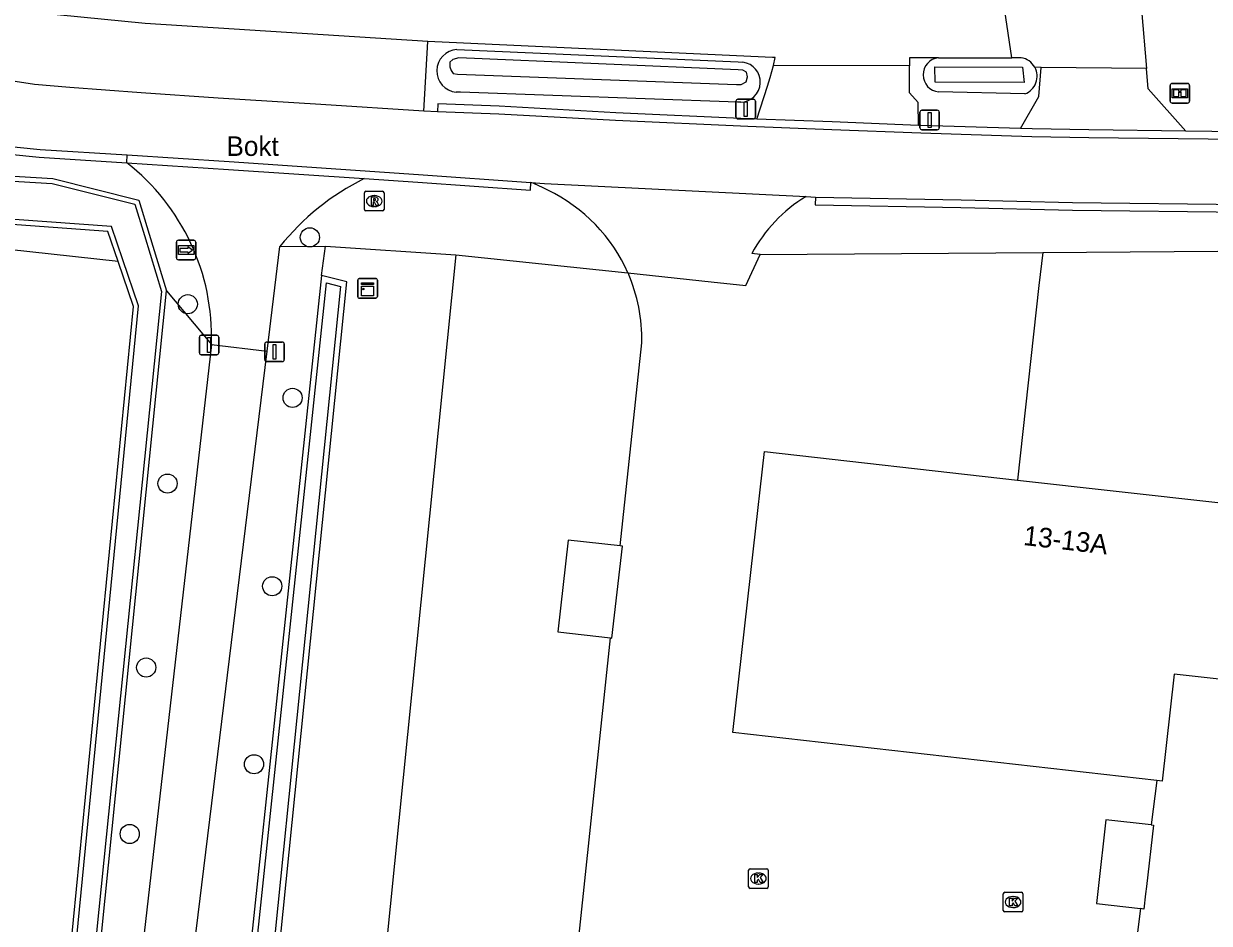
# Model space of a CAD drawing. Extents: x 162515 to 163909, y 388494 to 389773.
# Drawn here: x 162964.9 to 163025.4, y 388929.3 to 388975.3 of the extents above; entities that cross this region are included whole.
import ezdxf

# ---------------------------------------------------------------- set-up
doc = ezdxf.new("R2010")
doc.units = 0
for name, color, linetype in [('IMGEO_Afsluitpaal', 7, 'Continuous'), ('IMGEO_Boom', 7, 'Continuous'), ('IMGEO_Erf', 7, 'Continuous'), ('IMGEO_Grasland_agrarisch', 7, 'Continuous'), ('IMGEO_Grasland_overig', 7, 'Continuous'), ('IMGEO_Groenvoorziening', 7, 'Continuous'), ('IMGEO_Informatiebord', 7, 'Continuous'), ('IMGEO_Kast', 7, 'Continuous'), ('IMGEO_Kolk', 7, 'Continuous'), ('IMGEO_Loofbos', 7, 'Continuous'), ('IMGEO_Openbare_ruimte_label', 7, 'Continuous'), ('IMGEO_Pand', 7, 'Continuous'), ('IMGEO_Pand_nummerreeks', 7, 'Continuous'), ('IMGEO_Rijbaan_lokaal_gesloten', 7, 'Continuous'), ('IMGEO_Rijbaan_lokaal_halfverhard', 7, 'Continuous'), ('IMGEO_Rijbaan_lokaal_onverhard', 7, 'Continuous'), ('IMGEO_Rijbaan_lokaal_open', 7, 'Continuous'), ('IMGEO_Rioolput', 7, 'Continuous'), ('IMGEO_Waterloop', 7, 'Continuous'), ('IMGEO_Wegwijzer', 7, 'Continuous')]:
    doc.layers.add(name, color=color, linetype=linetype)

msp = doc.modelspace()

# ---------------------------------------------------------------- linework, layer by layer
at = {"layer": 'IMGEO_Afsluitpaal'}
for p, q in [((163001.263, 388970.503), (163001.263, 388971.303)), ((163001.263, 388971.303), (163001.263, 388970.503)), ((163001.363, 388971.403), (163002.153, 388971.403)), ((163002.153, 388971.403), (163001.363, 388971.403)), ((163002.253, 388971.303), (163002.253, 388970.503)), ((163002.253, 388970.503), (163002.253, 388971.303)), ((163010.652, 388969.946), (163010.652, 388970.746)), ((163010.652, 388970.746), (163010.652, 388969.946)), ((163010.752, 388970.846), (163011.542, 388970.846)), ((163011.542, 388970.846), (163010.752, 388970.846)), ((163011.642, 388970.746), (163011.642, 388969.946)), ((163011.642, 388969.946), (163011.642, 388970.746)), ((163002.153, 388970.403), (163001.363, 388970.403)), ((163001.363, 388970.403), (163002.153, 388970.403)), ((163011.542, 388969.846), (163010.752, 388969.846)), ((163010.752, 388969.846), (163011.542, 388969.846)), ((162973.867, 388958.456), (162973.867, 388959.256)), ((162973.867, 388959.256), (162973.867, 388958.456)), ((162973.967, 388959.356), (162974.757, 388959.356)), ((162974.757, 388959.356), (162973.967, 388959.356)), ((162974.857, 388959.256), (162974.857, 388958.456)), ((162974.857, 388958.456), (162974.857, 388959.256)), ((162977.21, 388958.108), (162977.21, 388958.908)), ((162977.21, 388958.908), (162977.21, 388958.108)), ((162977.31, 388959.008), (162978.1, 388959.008)), ((162978.1, 388959.008), (162977.31, 388959.008)), ((162978.2, 388958.908), (162978.2, 388958.108)), ((162978.2, 388958.108), (162978.2, 388958.908)), ((162974.757, 388958.356), (162973.967, 388958.356)), ((162973.967, 388958.356), (162974.757, 388958.356)), ((162978.1, 388958.008), (162977.31, 388958.008)), ((162977.31, 388958.008), (162978.1, 388958.008))]:
    msp.add_line(p, q, dxfattribs=at)
for points in [[(163001.683, 388971.278), (163001.833, 388971.278), (163001.833, 388970.528), (163001.683, 388970.528), (163001.683, 388971.278)], [(163011.072, 388970.721), (163011.222, 388970.721), (163011.222, 388969.971), (163011.072, 388969.971), (163011.072, 388970.721)], [(162974.287, 388959.231), (162974.437, 388959.231), (162974.437, 388958.481), (162974.287, 388958.481), (162974.287, 388959.231)], [(162977.63, 388958.883), (162977.78, 388958.883), (162977.78, 388958.133), (162977.63, 388958.133), (162977.63, 388958.883)]]:
    msp.add_lwpolyline(points, dxfattribs=at)
for centre, start, end in [((163001.363, 388971.303), 90, 180), ((163001.363, 388971.303), 90, 180), ((163002.153, 388971.303), 0, 90), ((163002.153, 388971.303), 360, 90), ((163010.752, 388970.746), 90, 180), ((163010.752, 388970.746), 90, 180), ((163011.542, 388970.746), 0, 90), ((163011.542, 388970.746), 360, 90), ((163001.363, 388970.503), 180, 270), ((163001.363, 388970.503), 180, 270), ((163002.153, 388970.503), 270, 0), ((163002.153, 388970.503), 270, 0), ((163010.752, 388969.946), 180, 270), ((163010.752, 388969.946), 180, 270), ((163011.542, 388969.946), 270, 0), ((163011.542, 388969.946), 270, 0), ((162973.967, 388959.256), 90, 180), ((162973.967, 388959.256), 90, 180), ((162974.757, 388959.256), 0, 90), ((162974.757, 388959.256), 360, 90), ((162977.31, 388958.908), 90, 180), ((162977.31, 388958.908), 90, 180), ((162978.1, 388958.908), 0, 90), ((162978.1, 388958.908), 360, 90), ((162973.967, 388958.456), 180, 270), ((162973.967, 388958.456), 180, 270), ((162974.757, 388958.456), 270, 0), ((162974.757, 388958.456), 270, 0), ((162977.31, 388958.108), 180, 270), ((162977.31, 388958.108), 180, 270), ((162978.1, 388958.108), 270, 0), ((162978.1, 388958.108), 270, 0)]:
    msp.add_arc(centre, 0.1, start, end, dxfattribs=at)
at = {"layer": 'IMGEO_Boom'}
for centre in [(162979.51, 388964.352), (162973.276, 388960.939), (162978.627, 388956.157), (162972.241, 388951.779), (162977.588, 388946.536), (162971.154, 388942.386), (162976.658, 388937.446), (162970.312, 388933.887)]:
    msp.add_circle(centre, 0.489, dxfattribs=at)
at = {"layer": 'IMGEO_Erf'}
for points in [[(163015.346, 388973.525), (163010.383, 389006.948)], [(163011.598, 388973.525), (163015.346, 388973.525)], [(163015.826, 388973.525), (163015.346, 388973.525)], [(163016.933, 388963.586), (163016.732, 388961.895), (163015.629, 388951.954)], [(162995.356, 388948.595), (162996.452, 388958.963)], [(162990.226, 388900.063), (162994.86, 388943.901)], [(163022.747, 388936.621), (163022.461, 388934.353)], [(163021.922, 388930.074), (163020.882, 388921.826), (163013.048, 388922.764)]]:
    msp.add_lwpolyline(points, dxfattribs=at)
for centre, radius, start, end in [((163015.679, 388972.578), 0.958, 28.60141, 81.17112), ((162988.096, 388959.176), 8.359, 358.54008, 23.67827)]:
    msp.add_arc(centre, radius, start, end, dxfattribs=at)
at = {"layer": 'IMGEO_Grasland_agrarisch'}
msp.add_lwpolyline([(162965.269, 388906.51), (162965.295, 388907.571), (162970.507, 388960.823), (162969.722, 388963.115)], dxfattribs=at)
at = {"layer": 'IMGEO_Grasland_overig'}
for points in [[(163021.967, 388975.964), (163022.225, 388972.97)], [(162925.982, 388975.254), (162939.232, 388969.776), (162946.964, 388968.638), (162951.321, 388968.254), (162966.391, 388967.363), (162970.783, 388966.255), (162971.31, 388964.515), (162972.188, 388961.62)], [(162969.722, 388963.115), (162969.194, 388964.658), (162943.616, 388966.516), (162926.272, 388973.119), (162925.379, 388974.383)], [(163003.178, 388973.126), (163003.268, 388973.532), (163003.132, 388973.537), (162985.891, 388974.332), (162985.529, 388974.355)], [(162987.016, 388973.945), (163001.376, 388973.31), (163001.616, 388973.299)], [(163011.598, 388973.525), (163010.129, 388973.525), (163010.129, 388973.107)], [(162969.722, 388963.115), (162943.576, 388965.984), (162934.148, 388968.56), (162924.889, 388971.244), (162921.313, 388972.477), (162913.718, 388966.327), (162905.083, 388967.364), (162899.047, 388963.626), (162890.416, 388958.224), (162881.009, 388955.532), (162875.047, 388956.022), (162874.432, 388960.337)], [(163016.852, 388973.034), (163016.52, 388973.037)], [(163001.508, 388971.256), (163001.35, 388971.262), (162987.194, 388971.761), (162986.975, 388971.769)], [(163016.018, 388971.682), (163011.61, 388971.781)], [(162977.98, 388963.885), (162980.313, 388963.907)], [(162986.956, 388963.458), (162995.751, 388962.533)], [(163002.495, 388963.475), (163016.933, 388963.586)], [(163016.933, 388963.586), (163037.03, 388963.741), (163052.129, 388961.909), (163052.955, 388961.925)], [(162972.188, 388961.62), (162974.481, 388958.888)]]:
    msp.add_lwpolyline(points, dxfattribs=at)
for centre, radius, start, end in [((162987.077, 388972.855), 1.091, 93.19275, 264.64839), ((163001.478, 388972.282), 1.026, 271.69795, 82.24998), ((163011.698, 388972.654), 0.877, 96.55393, 264.23453), ((163015.683, 388972.577), 0.956, 290.54795, 28.79476)]:
    msp.add_arc(centre, radius, start, end, dxfattribs=at)
at = {"layer": 'IMGEO_Groenvoorziening'}
for points in [[(162980.096, 388962.403), (162974.2, 388906.548)], [(162966.787, 388908.195), (162972.188, 388961.62)]]:
    msp.add_lwpolyline(points, dxfattribs=at)
at = {"layer": 'IMGEO_Informatiebord'}
for p, q in [((163023.432, 388971.313), (163023.432, 388972.113)), ((163023.432, 388972.113), (163023.432, 388971.313)), ((163023.532, 388972.213), (163024.322, 388972.213)), ((163024.322, 388972.213), (163023.532, 388972.213)), ((163024.422, 388972.113), (163024.422, 388971.313)), ((163024.422, 388971.313), (163024.422, 388972.113)), ((163024.322, 388971.213), (163023.532, 388971.213)), ((163023.532, 388971.213), (163024.322, 388971.213))]:
    msp.add_line(p, q, dxfattribs=at)
for points in [[(163023.533, 388971.945), (163024.321, 388971.945), (163024.321, 388971.481), (163023.533, 388971.481), (163023.533, 388971.945)], [(163023.598, 388971.88), (163023.598, 388971.546), (163023.873, 388971.546), (163023.874, 388971.759), (163023.978, 388971.76), (163023.979, 388971.546), (163024.256, 388971.546), (163024.256, 388971.88), (163023.98, 388971.88), (163023.98, 388971.8), (163023.874, 388971.8), (163023.874, 388971.88), (163023.598, 388971.88)]]:
    msp.add_lwpolyline(points, dxfattribs=at)
for centre, start, end in [((163023.532, 388972.113), 90, 180), ((163023.532, 388972.113), 90, 180), ((163024.322, 388972.113), 0, 90), ((163024.322, 388972.113), 360, 90), ((163023.532, 388971.313), 180, 270), ((163023.532, 388971.313), 180, 270), ((163024.322, 388971.313), 270, 0), ((163024.322, 388971.313), 270, 0)]:
    msp.add_arc(centre, 0.1, start, end, dxfattribs=at)
at = {"layer": 'IMGEO_Kast'}
for p, q in [((162982.03, 388962.249), (162982.871, 388962.249)), ((162982.871, 388962.249), (162982.03, 388962.249)), ((162981.955, 388961.324), (162981.955, 388962.165)), ((162981.955, 388962.165), (162981.955, 388961.324)), ((162982.955, 388962.174), (162982.955, 388961.333)), ((162982.955, 388961.333), (162982.955, 388962.174)), ((162982.88, 388961.249), (162982.039, 388961.249)), ((162982.039, 388961.249), (162982.88, 388961.249))]:
    msp.add_line(p, q, dxfattribs=at)
for points in [[(162982.15, 388962.039), (162982.75, 388962.039), (162982.75, 388961.954), (162982.15, 388961.954), (162982.15, 388962.039)], [(162982.15, 388961.864), (162982.75, 388961.864), (162982.75, 388961.375), (162982.15, 388961.375), (162982.15, 388961.864)]]:
    msp.add_lwpolyline(points, dxfattribs=at)
msp.add_circle((162982.234, 388961.713), 0.0377, dxfattribs=at)
for centre, start, end in [((162982.033, 388962.171), 92.4484, 184.28452), ((162982.033, 388962.171), 92.4484, 184.28452), ((162982.877, 388962.171), 2.4484, 94.28452), ((162982.877, 388962.171), 2.4484, 94.28452), ((162982.033, 388961.327), 182.4484, 274.28452), ((162982.033, 388961.327), 182.4484, 274.28452), ((162982.877, 388961.327), 272.4484, 4.28452), ((162982.877, 388961.327), 272.4484, 4.28452)]:
    msp.add_arc(centre, 0.0779, start, end, dxfattribs=at)
at = {"layer": 'IMGEO_Kolk'}
for p, q in [((163001.909, 388931.184), (163001.909, 388932.036)), ((163001.984, 388932.11), (163002.836, 388932.11)), ((163002.91, 388932.036), (163002.91, 388931.184)), ((163002.42, 388931.33), (163002.395, 388931.33)), ((163002.397, 388931.89), (163002.422, 388931.89)), ((163002.836, 388931.11), (163001.984, 388931.11)), ((163014.913, 388929.984), (163014.913, 388930.836)), ((163014.988, 388930.91), (163015.84, 388930.91)), ((163015.914, 388930.836), (163015.914, 388929.984)), ((163015.424, 388930.13), (163015.399, 388930.13)), ((163015.401, 388930.69), (163015.426, 388930.69)), ((163015.84, 388929.91), (163014.988, 388929.91))]:
    msp.add_line(p, q, dxfattribs=at)
for points in [[(163001.909, 388931.184), (163001.909, 388932.036)], [(163001.984, 388932.11), (163002.836, 388932.11)], [(163002.91, 388932.036), (163002.91, 388931.184)], [(163002.23, 388931.81), (163002.353, 388931.81), (163002.353, 388931.659), (163002.483, 388931.81), (163002.647, 388931.81), (163002.501, 388931.659), (163002.654, 388931.41), (163002.502, 388931.41), (163002.417, 388931.574), (163002.353, 388931.507), (163002.353, 388931.41), (163002.23, 388931.41), (163002.23, 388931.81)], [(163002.836, 388931.11), (163001.984, 388931.11)], [(163014.913, 388929.984), (163014.913, 388930.836)], [(163014.988, 388930.91), (163015.84, 388930.91)], [(163015.914, 388930.836), (163015.914, 388929.984)], [(163015.234, 388930.61), (163015.357, 388930.61), (163015.357, 388930.459), (163015.487, 388930.61), (163015.651, 388930.61), (163015.505, 388930.459), (163015.658, 388930.21), (163015.506, 388930.21), (163015.421, 388930.374), (163015.357, 388930.307), (163015.357, 388930.21), (163015.234, 388930.21), (163015.234, 388930.61)], [(163015.84, 388929.91), (163014.988, 388929.91)]]:
    msp.add_lwpolyline(points, dxfattribs=at)
for centre, start, end in [((163001.986, 388932.034), 91.55205, 178.44795), ((163001.986, 388932.034), 91.55205, 178.44795), ((163002.834, 388932.034), 1.55205, 88.44795), ((163002.834, 388932.034), 1.55205, 88.44795), ((163001.986, 388931.186), 181.55205, 268.44795), ((163001.986, 388931.186), 181.55205, 268.44795), ((163002.834, 388931.186), 271.55205, 358.44795), ((163002.834, 388931.186), 271.55205, 358.44795), ((163014.99, 388930.834), 91.55205, 178.44795), ((163014.99, 388930.834), 91.55205, 178.44795), ((163015.838, 388930.834), 1.55205, 88.44795), ((163015.838, 388930.834), 1.55205, 88.44795), ((163014.99, 388929.986), 181.55205, 268.44795), ((163014.99, 388929.986), 181.55205, 268.44795), ((163015.838, 388929.986), 271.55205, 358.44795), ((163015.838, 388929.986), 271.55205, 358.44795)]:
    msp.add_arc(centre, 0.0765, start, end, dxfattribs=at)
for centre, major_axis, ratio, start_param, end_param in [((163002.396, 388931.61), (-0.387, 0.002), 0.722429, 4.712389, 7.853982), ((163002.421, 388931.61), (-0.39, 0.002), 0.717154, 1.570796, 4.712389), ((163015.4, 388930.41), (-0.387, 0.002), 0.722429, 4.712389, 7.853982), ((163015.425, 388930.41), (-0.39, 0.002), 0.717154, 1.570796, 4.712389)]:
    msp.add_ellipse(centre, major_axis=major_axis, ratio=ratio, start_param=start_param, end_param=end_param, dxfattribs=at)
at = {"layer": 'IMGEO_Loofbos'}
for points in [[(162980.096, 388962.403), (162980.313, 388963.907)], [(162980.313, 388963.907), (162986.956, 388963.458)], [(162986.956, 388963.458), (162980.697, 388901.303), (162990.226, 388900.063)], [(162975.806, 388906.861), (162981.389, 388962.074), (162980.096, 388962.403)]]:
    msp.add_lwpolyline(points, dxfattribs=at)
at = {"layer": 'IMGEO_Pand'}
for points in [[(163022.747, 388936.621), (163001.105, 388939.069), (163002.165, 388948.444), (163002.726, 388953.412), (163015.629, 388951.954)], [(163015.629, 388951.954), (163036.085, 388949.677), (163035.083, 388940.766), (163023.643, 388942.053), (163023.027, 388936.591), (163022.747, 388936.621)], [(162995.356, 388948.595), (162992.701, 388948.895), (162992.171, 388944.205), (162994.86, 388943.901)], [(162994.86, 388943.901), (162994.932, 388943.893), (162995.462, 388948.583), (162995.356, 388948.595)], [(163022.461, 388934.353), (163020.152, 388934.613), (163019.756, 388931.104), (163019.669, 388930.328), (163021.922, 388930.074)], [(163022.461, 388934.353), (163022.572, 388934.34), (163022.219, 388931.205), (163022.177, 388930.832), (163022.089, 388930.055), (163021.922, 388930.074)]]:
    msp.add_lwpolyline(points, dxfattribs=at)
at = {"layer": 'IMGEO_Rijbaan_lokaal_gesloten'}
for points in [[(162985.329, 388970.797), (162980.065, 388971.129), (162974.827, 388971.464), (162970.89, 388971.741), (162967.254, 388971.997), (162965.448, 388972.167), (162962.802, 388972.559)], [(162947.161, 388970.98), (162953.292, 388970.102), (162965.732, 388968.844), (162970.174, 388968.559)], [(162986.023, 388970.77), (162985.329, 388970.797)], [(163060.658, 388969.221), (163043.395, 388969.279), (163026.878, 388969.344), (163019.275, 388969.441), (163016.375, 388969.489), (163010.694, 388969.666), (163006.164, 388969.852), (163001.869, 388970.009), (162995.115, 388970.321), (162989.16, 388970.649), (162986.023, 388970.77)], [(162970.174, 388968.559), (162975.389, 388968.225), (162985.053, 388967.564), (162990.798, 388967.159)], [(162990.798, 388967.159), (162991.481, 388967.111), (163004.846, 388966.436)], [(163004.846, 388966.436), (163005.318, 388966.412)], [(163005.318, 388966.412), (163012.759, 388966.272), (163018.447, 388966.138), (163027.251, 388966.034), (163035.819, 388965.997), (163049.064, 388965.828), (163059.249, 388965.846), (163068.574, 388965.898)]]:
    msp.add_lwpolyline(points, dxfattribs=at)
at = {"layer": 'IMGEO_Rijbaan_lokaal_halfverhard'}
for points in [[(163002.329, 388970.393), (163001.887, 388970.409), (162995.137, 388970.72), (162989.175, 388971.049), (162986.049, 388971.17), (162986.023, 388970.77)], [(162947.107, 388970.584), (162953.235, 388969.706), (162965.692, 388968.446), (162970.158, 388968.16)], [(163015.793, 388969.908), (163010.71, 388970.066), (163010.586, 388970.071)], [(163060.659, 388969.621), (163043.397, 388969.679), (163026.883, 388969.744), (163024.225, 388969.778)], [(162970.158, 388968.16), (162970.174, 388968.559)], [(162970.158, 388968.16), (162975.363, 388967.826), (162982.289, 388967.352)], [(162982.289, 388967.352), (162985.026, 388967.165), (162990.776, 388966.76), (162990.798, 388967.159)], [(163005.318, 388966.412), (163005.306, 388966.012), (163012.75, 388965.872), (163018.442, 388965.738), (163027.249, 388965.634), (163035.814, 388965.597), (163049.249, 388965.428), (163059.251, 388965.446), (163068.575, 388965.498)], [(162977.325, 388958.54), (162977.98, 388963.885)], [(162974.481, 388958.888), (162977.325, 388958.54)]]:
    msp.add_lwpolyline(points, dxfattribs=at)
for centre, radius, start, end in [((162963.246, 388959.294), 11.242, 357.93274, 52.06112), ((162987.864, 388956.012), 12.636, 116.17917, 141.46079)]:
    msp.add_arc(centre, radius, start, end, dxfattribs=at)
at = {"layer": 'IMGEO_Rijbaan_lokaal_onverhard'}
for points in [[(162974.481, 388958.888), (162969.46, 388914.978)], [(162971.876, 388914.048), (162977.325, 388958.54)]]:
    msp.add_lwpolyline(points, dxfattribs=at)
at = {"layer": 'IMGEO_Rijbaan_lokaal_open'}
for points in [[(162985.529, 388974.355), (162971.105, 388975.277), (162964.53, 388975.919)], [(162985.329, 388970.797), (162985.529, 388974.355)], [(163002.329, 388970.393), (163002.878, 388972.071), (163003.004, 388972.514), (163003.178, 388973.126)], [(163010.129, 388973.107), (163003.178, 388973.126)], [(163010.586, 388970.071), (163010.565, 388971.246), (163010.129, 388971.728), (163010.129, 388972.36), (163010.129, 388973.107)], [(163015.793, 388969.908), (163016.718, 388971.543), (163016.852, 388973.034)], [(163022.225, 388972.97), (163016.852, 388973.034)], [(163024.225, 388969.778), (163022.314, 388971.933), (163022.225, 388972.97)], [(163010.586, 388970.071), (163006.179, 388970.252), (163002.329, 388970.393)], [(163024.225, 388969.778), (163019.282, 388969.841), (163016.387, 388969.889), (163015.793, 388969.908)], [(162995.751, 388962.533), (163000, 388962.087), (163001.763, 388961.901), (163002.495, 388963.475)], [(163002.495, 388963.475), (163002.071, 388963.522)]]:
    msp.add_lwpolyline(points, dxfattribs=at)
for centre, radius, start, end in [((162988.346, 388960.765), 6.848, 61.0111, 69.02025), ((162987.987, 388959.108), 8.486, 23.80716, 64.31717), ((163008.676, 388960.01), 7.481, 120.79766, 152.00161)]:
    msp.add_arc(centre, radius, start, end, dxfattribs=at)
at = {"layer": 'IMGEO_Rioolput'}
for p, q in [((162982.295, 388965.778), (162982.295, 388966.63)), ((162982.37, 388966.704), (162983.222, 388966.704)), ((162982.783, 388966.484), (162982.808, 388966.484)), ((162983.296, 388966.63), (162983.296, 388965.778)), ((162982.806, 388965.924), (162982.781, 388965.924)), ((162983.222, 388965.704), (162982.37, 388965.704))]:
    msp.add_line(p, q, dxfattribs=at)
for points in [[(162982.295, 388965.778), (162982.295, 388966.63)], [(162982.37, 388966.704), (162983.222, 388966.704)], [(162983.296, 388966.63), (162983.296, 388965.778)], [(162982.884, 388966.402), (162982.632, 388966.404), (162982.632, 388966.004)], [(162982.632, 388966.004), (162982.756, 388966.004), (162982.756, 388966.166), (162982.767, 388966.166)], [(162982.81, 388966.323), (162982.756, 388966.323), (162982.756, 388966.242)], [(162982.756, 388966.242), (162982.808, 388966.242)], [(162982.814, 388966.137), (162982.885, 388966.004), (162983.025, 388966.004), (162982.96, 388966.13)], [(162983.222, 388965.704), (162982.37, 388965.704)]]:
    msp.add_lwpolyline(points, dxfattribs=at)
for centre, radius, start, end in [((162982.372, 388966.628), 0.0765, 91.55205, 178.44795), ((162982.372, 388966.628), 0.0765, 91.55205, 178.44795), ((162983.22, 388966.628), 0.0765, 1.55205, 88.44795), ((162983.22, 388966.628), 0.0765, 1.55205, 88.44795), ((162982.766, 388966.113), 0.0533, 26.02933, 88.69889), ((162982.792, 388966.431), 0.19, 274.7715, 282.96867), ((162982.816, 388966.227), 0.0964, 77.00612, 93.18647), ((162982.83, 388966.284), 0.0378, 276.66336, 79.67722), ((162982.883, 388966.292), 0.109, 350.36119, 89.41601), ((162982.881, 388966.292), 0.112, 277.58423, 350.98172), ((162982.865, 388966.077), 0.108, 29.51342, 73.79051), ((162982.372, 388965.78), 0.0765, 181.55205, 268.44795), ((162982.372, 388965.78), 0.0765, 181.55205, 268.44795), ((162983.22, 388965.78), 0.0765, 271.55205, 358.44795), ((162983.22, 388965.78), 0.0765, 271.55205, 358.44795)]:
    msp.add_arc(centre, radius, start, end, dxfattribs=at)
for centre, major_axis, ratio, start_param, end_param in [((162982.782, 388966.204), (-0.387, 0.002), 0.722429, 4.712389, 7.853982), ((162982.807, 388966.204), (-0.39, 0.002), 0.717154, 1.570796, 4.712389)]:
    msp.add_ellipse(centre, major_axis=major_axis, ratio=ratio, start_param=start_param, end_param=end_param, dxfattribs=at)
at = {"layer": 'IMGEO_Waterloop'}
for points in [[(162925.911, 388975.006), (162939.163, 388969.527), (162946.934, 388968.383), (162951.302, 388967.998), (162966.352, 388967.108), (162970.579, 388966.042), (162971.064, 388964.44), (162971.927, 388961.595), (162966.53, 388908.206)], [(162965.551, 388907.555), (162970.768, 388960.853), (162969.965, 388963.198), (162969.382, 388964.902), (162943.672, 388966.769), (162926.437, 388973.331), (162925.55, 388974.52)], [(162987.054, 388972.689), (163001.285, 388972.156), (163001.532, 388972.156), (163001.779, 388972.299), (163001.857, 388972.546), (163001.805, 388972.78), (163001.61, 388972.884), (163001.371, 388972.91), (162987.106, 388973.521), (162986.807, 388973.443), (162986.651, 388973.3), (162986.651, 388973.066), (162986.716, 388972.871), (162986.82, 388972.728), (162987.054, 388972.689)], [(163015.98, 388972.253), (163011.439, 388972.282), (163011.418, 388973.063), (163015.884, 388973.045), (163015.98, 388972.253)], [(162974.497, 388906.543), (162980.354, 388962.032), (162981.069, 388961.85), (162975.51, 388906.87)]]:
    msp.add_lwpolyline(points, dxfattribs=at)
at = {"layer": 'IMGEO_Wegwijzer'}
for p, q in [((162972.696, 388963.306), (162972.696, 388964.106)), ((162972.696, 388964.106), (162972.696, 388963.306)), ((162972.796, 388964.206), (162973.586, 388964.206)), ((162973.586, 388964.206), (162972.796, 388964.206)), ((162973.686, 388964.106), (162973.686, 388963.306)), ((162973.686, 388963.306), (162973.686, 388964.106)), ((162973.586, 388963.206), (162972.796, 388963.206)), ((162972.796, 388963.206), (162973.586, 388963.206))]:
    msp.add_line(p, q, dxfattribs=at)
for points in [[(162972.797, 388963.938), (162973.585, 388963.938), (162973.585, 388963.474), (162972.797, 388963.474), (162972.797, 388963.938)], [(162972.862, 388963.79), (162972.862, 388963.706), (162972.862, 388963.622), (162973.273, 388963.622), (162973.273, 388963.539), (162973.52, 388963.706), (162973.273, 388963.873), (162973.273, 388963.79), (162972.862, 388963.79)]]:
    msp.add_lwpolyline(points, dxfattribs=at)
for centre, start, end in [((162972.796, 388964.106), 90, 180), ((162972.796, 388964.106), 90, 180), ((162973.586, 388964.106), 0, 90), ((162973.586, 388964.106), 360, 90), ((162972.796, 388963.306), 180, 270), ((162972.796, 388963.306), 180, 270), ((162973.586, 388963.306), 270, 0), ((162973.586, 388963.306), 270, 0)]:
    msp.add_arc(centre, 0.1, start, end, dxfattribs=at)

# ---------------------------------------------------------------- texts
at = {"layer": 'IMGEO_Openbare_ruimte_label'}
msp.add_text('Bokt', height=1, dxfattribs=at).set_placement((162975.246, 388968.512))
at = {"layer": 'IMGEO_Pand_nummerreeks'}
msp.add_text('13-13A', height=1, rotation=353.53188, dxfattribs=at).set_placement((163015.905, 388948.646))

doc.saveas('drawing.dxf')
